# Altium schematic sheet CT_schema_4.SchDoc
size 368 x 309 mm
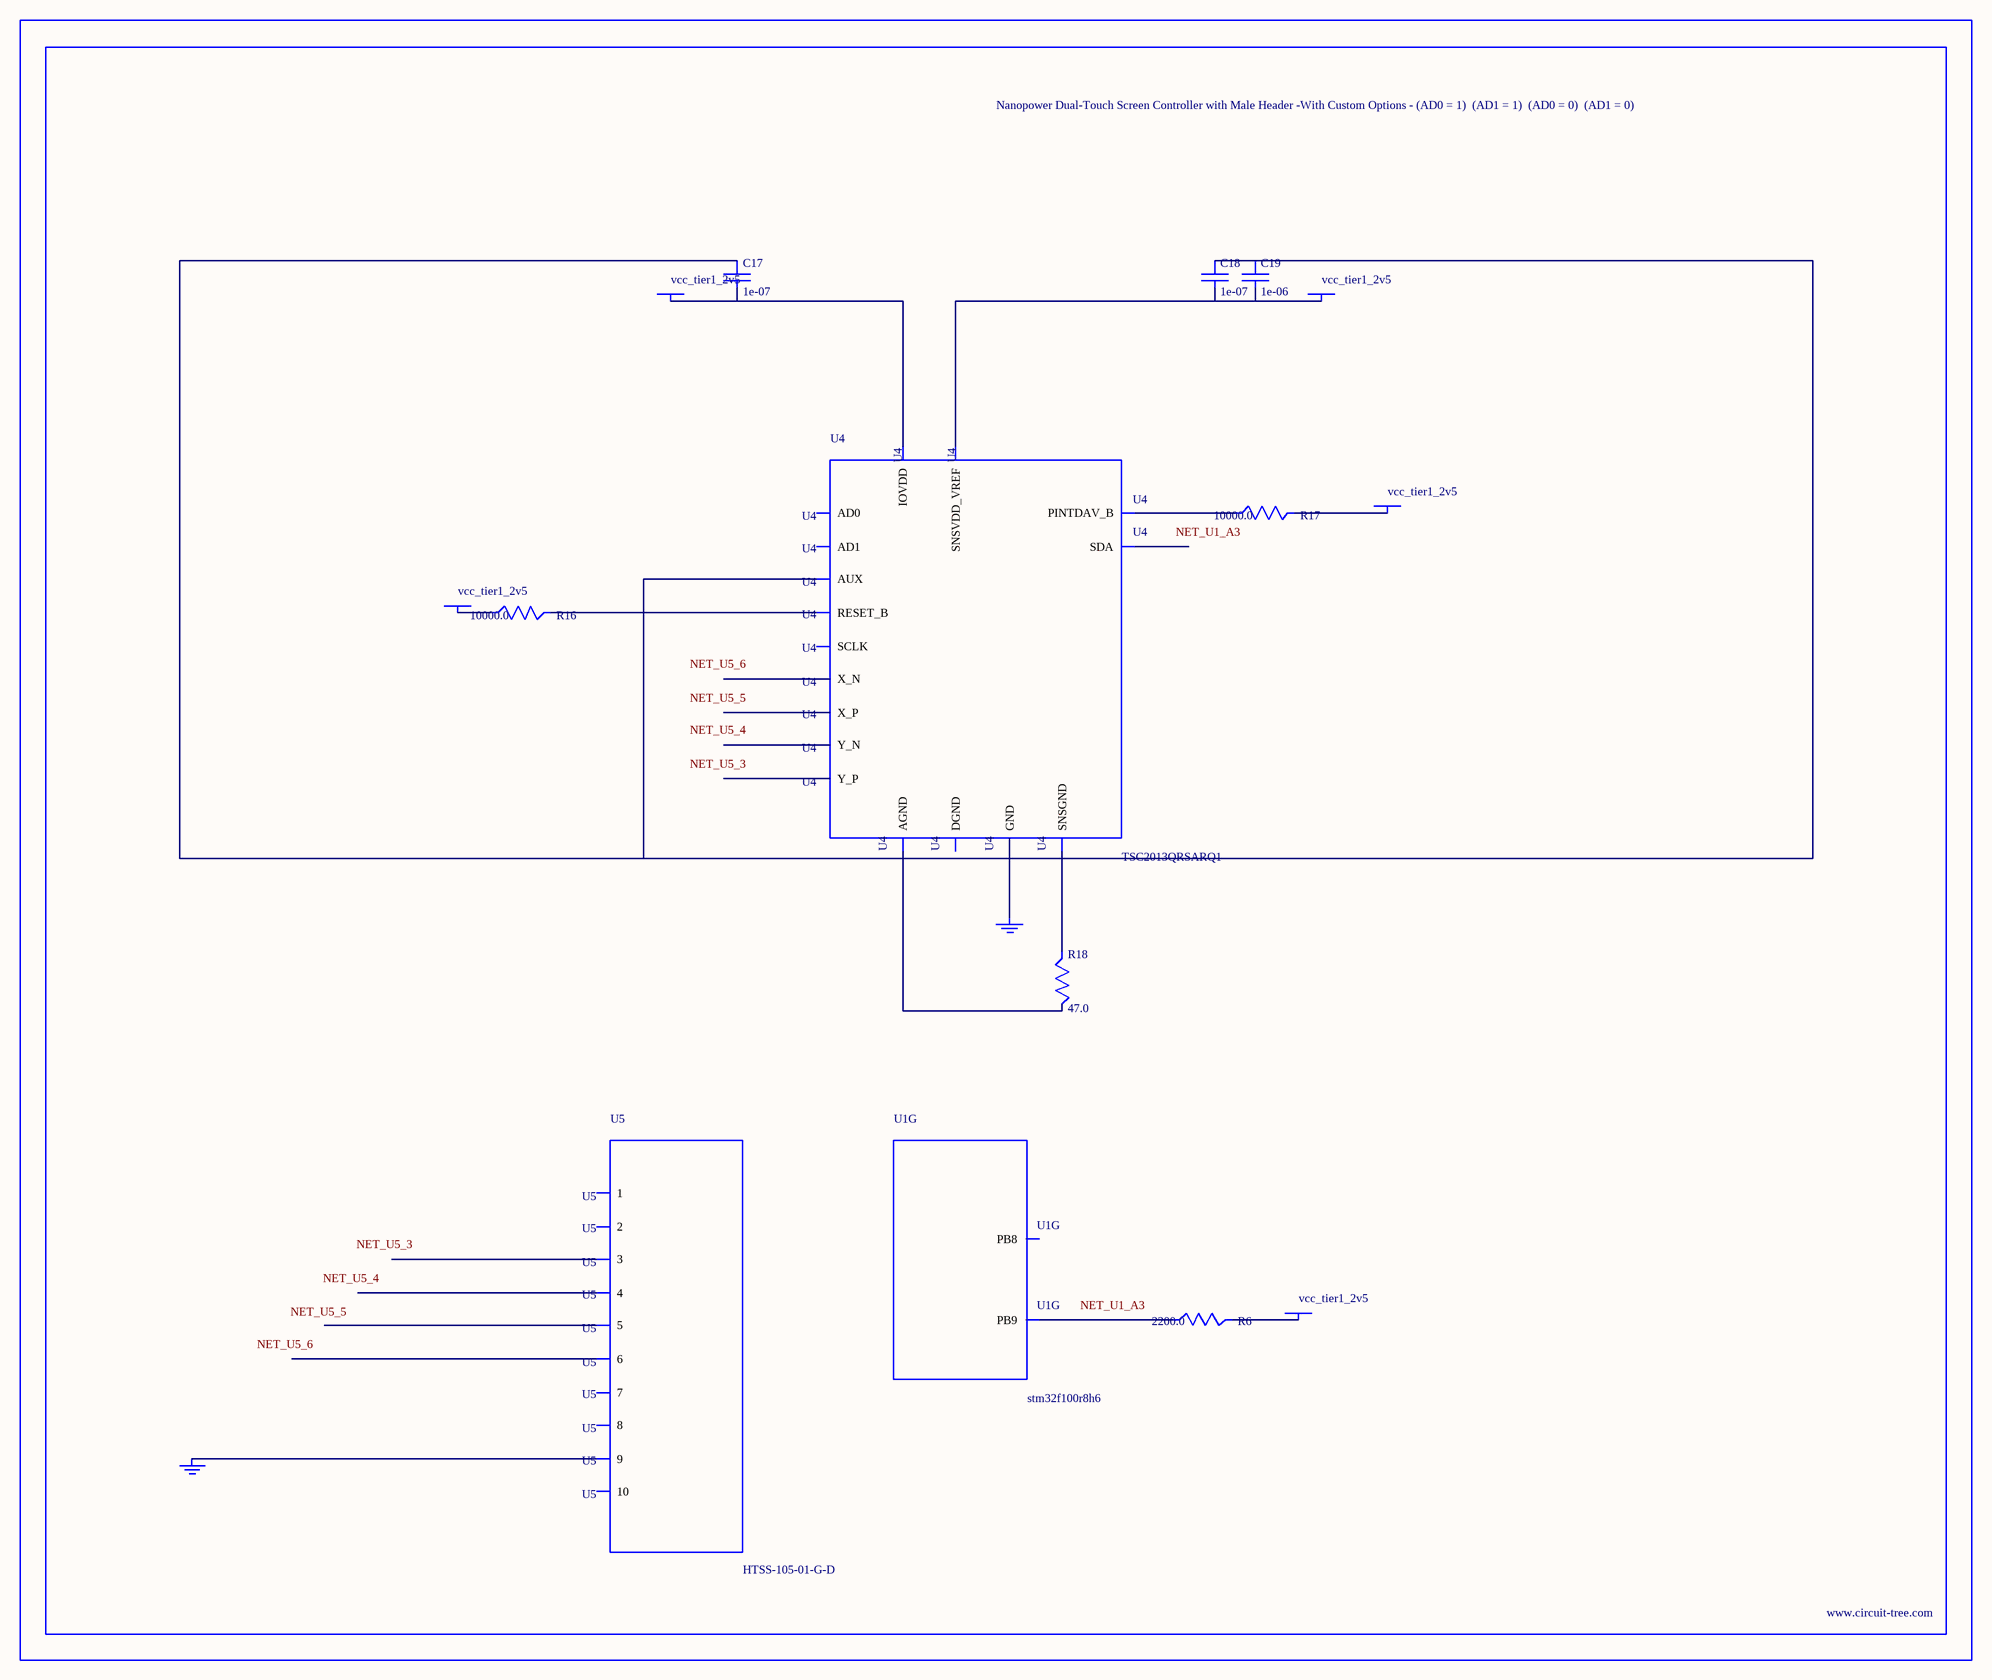
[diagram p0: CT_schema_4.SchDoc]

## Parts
BORDER3  (no value)
C17  1e-07  [C0402]
C18  1e-07  [C0402]
C19  1e-06  [C0603]
GND_INSTANCE_3_0  (no value)
GND_INSTANCE_3_1  (no value)
POWER_INSTANCE_3_0  vcc_tier1_2v5
POWER_INSTANCE_3_1  vcc_tier1_2v5
POWER_INSTANCE_3_2  vcc_tier1_2v5
POWER_INSTANCE_3_3  vcc_tier1_2v5
POWER_INSTANCE_3_4  vcc_tier1_2v5
R6  2200.0  [R0603]
R16  10000.0  [R0603]
R17  10000.0  [R0603]
R18  47.0  [R0603]
U1  stm32f100r8h6  [TFBGA64]  (part G of 7)
U4  TSC2013QRSARQ1  [QFN65P400X400X100-17N]
U5  HTSS-105-01-G-D  [HTSS-105-01-G-D]

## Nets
NetC17_1: C17.1 C18.1 C19.1 R18.1 R18.2 U4.8(AUX) U4.9(AGND) U4.15(SNSGND)
NetC17_2: C17.2 POWER_INSTANCE_3_2.0(PWR) U4.7(IOVDD)
NetC18_2: C18.2 C19.2 POWER_INSTANCE_3_3.0(PWR) U4.10(SNSVDD_VREF)
NetGND_INSTANCE_3_0_0: GND_INSTANCE_3_0.0(GND) U4.17(GND)
NetGND_INSTANCE_3_1_0: GND_INSTANCE_3_1.0(GND) U5.9
NetPOWER_INSTANCE_3_0_0: POWER_INSTANCE_3_0.0(PWR) R17.2
NetPOWER_INSTANCE_3_1_0: POWER_INSTANCE_3_1.0(PWR) R16.1
NetPOWER_INSTANCE_3_4_0: POWER_INSTANCE_3_4.0(PWR) R6.2
NetR6_1: R6.1 U1.A3(PB9)
NetR16_2: R16.2 U4.5(RESET_B)
NetR17_1: R17.1 U4.4(PINTDAV_B)

Not connected (* = marked no-connect by the designer): U1 B3(PB8); U4 1(SDA) 2(SCLK) 3(AD1) 6(DGND) 11(X_P) 12(Y_P) 13(X_N) 14(Y_N) 16(AD0); U5 1 2 3 4 5 6 7 8 10

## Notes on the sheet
- Labels drawn without touching a wire or pin: NET_U1_A3, NET_U5_3, NET_U5_4, NET_U5_5, NET_U5_6

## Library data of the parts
BORDER3 = BORDER_PAGE3
C17 C18 = C0402C104K3RACTU
C19 = C0603C105K3RACTU
GND_INSTANCE_3_0 GND_INSTANCE_3_1 = GND
POWER_INSTANCE_3_0-POWER_INSTANCE_3_4 = PWR
R6 = RC0603JR-072K2L
R16 R17 = RC0603JR-0710KL
R18 = RC0603JR-0747RL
